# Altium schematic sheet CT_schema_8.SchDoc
size 278 x 170 mm
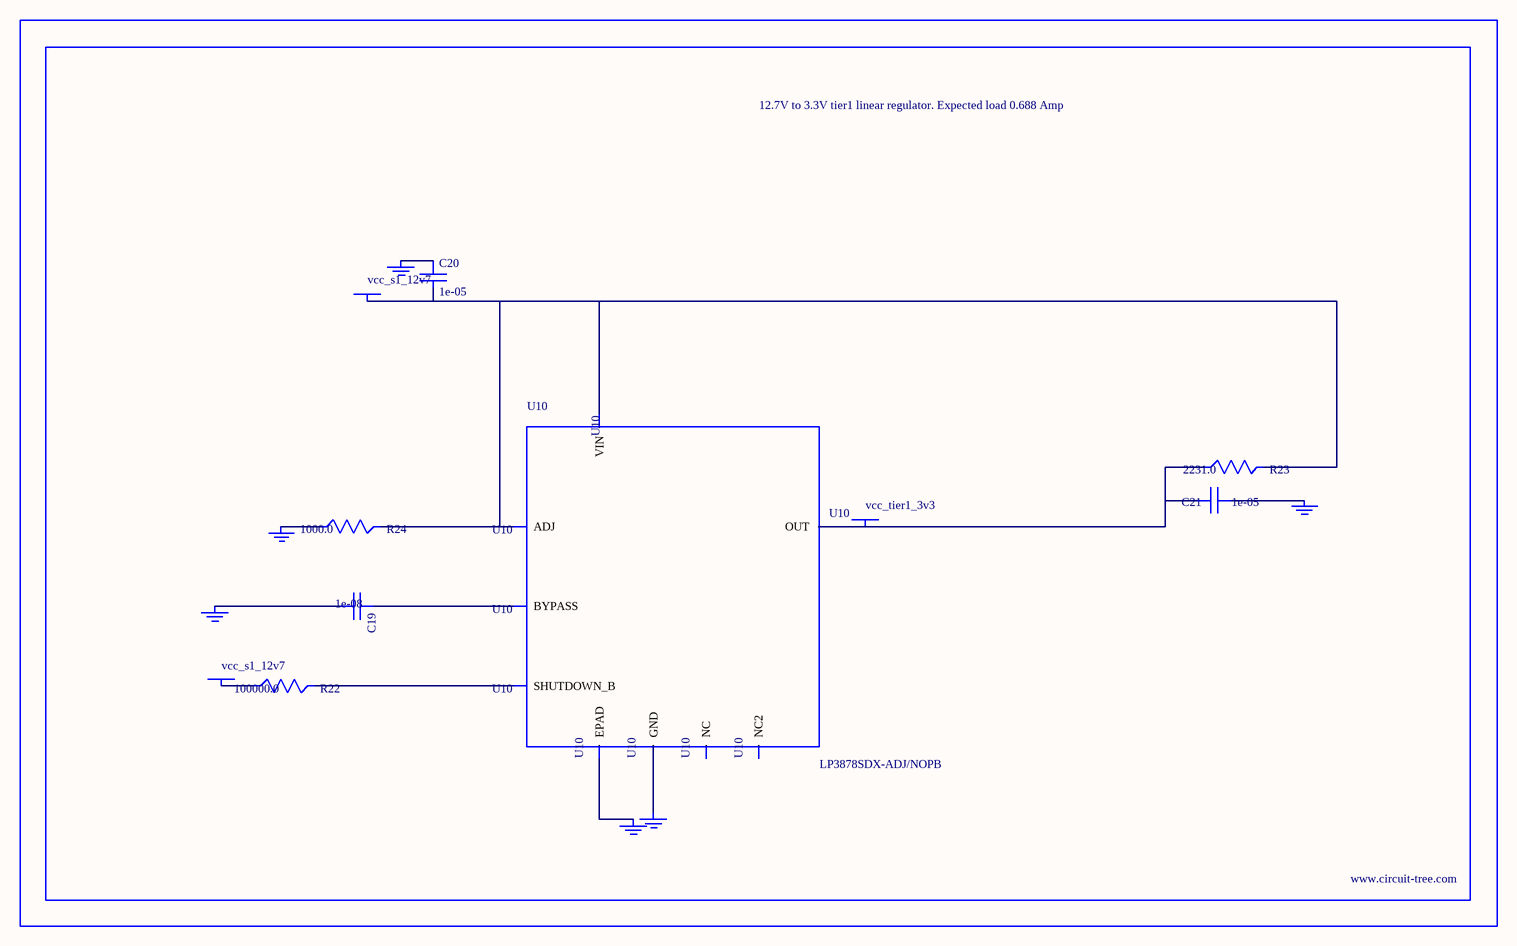
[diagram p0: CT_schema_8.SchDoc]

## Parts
BORDER7  (no value)
C19  1e-08  [C0402]
C20  1e-05  [C1210]
C21  1e-05  [C1210]
GND_INSTANCE_7_0  (no value)
GND_INSTANCE_7_1  (no value)
GND_INSTANCE_7_2  (no value)
GND_INSTANCE_7_3  (no value)
GND_INSTANCE_7_4  (no value)
GND_INSTANCE_7_5  (no value)
POWER_INSTANCE_7_0  vcc_s1_12v7
POWER_INSTANCE_7_1  vcc_s1_12v7
POWER_INSTANCE_7_2  vcc_tier1_3v3
R22  100000.0  [R0603]
R23  2231.0  [R0603]
R24  1000.0  [R0603]
U10  LP3878SDX-ADJ/NOPB  [WSON-8]

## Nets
NetC19_1: C19.1 U10.1(BYPASS)
NetC19_2: C19.2 GND_INSTANCE_7_0.0(GND)
NetC20_1: C20.1 GND_INSTANCE_7_1.0(GND)
NetC20_2: C20.2 POWER_INSTANCE_7_0.0(PWR) R23.2 R24.2 U10.4(VIN) U10.6(ADJ)
NetC21_1: C21.1 GND_INSTANCE_7_2.0(GND)
NetC21_2: C21.2 POWER_INSTANCE_7_2.0(PWR) R23.1 U10.5(OUT)
NetGND_INSTANCE_7_3_0: GND_INSTANCE_7_3.0(GND) R24.1
NetGND_INSTANCE_7_4_0: GND_INSTANCE_7_4.0(GND) U10.PAD(EPAD)
NetGND_INSTANCE_7_5_0: GND_INSTANCE_7_5.0(GND) U10.3(GND)
NetPOWER_INSTANCE_7_1_0: POWER_INSTANCE_7_1.0(PWR) R22.1
NetR22_2: R22.2 U10.8(SHUTDOWN_B)

Not connected (* = marked no-connect by the designer): U10 2(NC) 7(NC2)

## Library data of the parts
BORDER7 = BORDER_PAGE7
C19 = C0402C103K3RAC
C20 = C1210C106K5PACTU
C21 = GRM32DR61E106MA12L
GND_INSTANCE_7_0-GND_INSTANCE_7_5 = GND
POWER_INSTANCE_7_0-POWER_INSTANCE_7_2 = PWR
R22 = RC0603JR-07100KL
R23 = R23
R24 = RC0603JR-071KL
